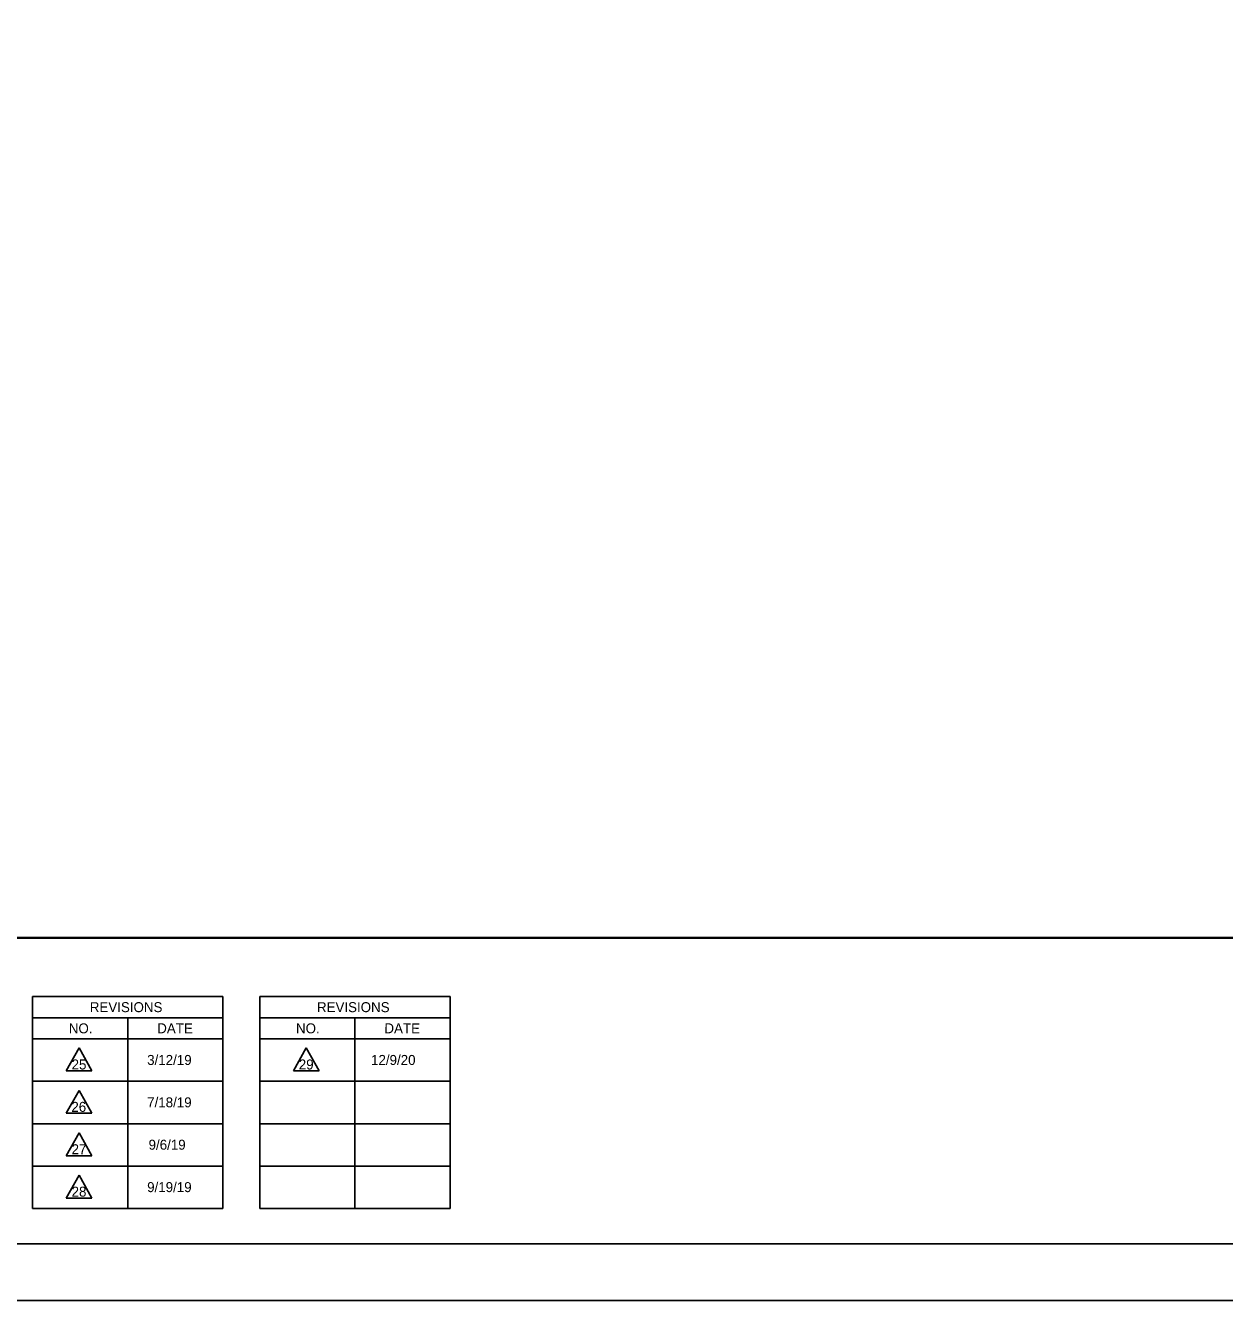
# Model space of a CAD drawing. Extents: x -2251 to 10196, y -13470 to 1199.
# Drawn here: x 750 to 1279, y -2926 to -2363 of the extents above; entities that cross this region are included whole.
import ezdxf

# ---------------------------------------------------------------- set-up
doc = ezdxf.new("R2010")
doc.units = 0
for name, color, linetype in [('RD_SHT_Bndy', 7, 'Continuous'), ('RD_SHT_Iplotshp', 7, 'Continuous'), ('RD_SHT_Misc1', 7, 'Continuous'), ('RD_SHT_Snap', 7, 'Continuous'), ('RD_SHT_TX', 7, 'Continuous'), ('RD_TX_RoadID', 7, 'Continuous')]:
    doc.layers.add(name, color=color, linetype=linetype)

msp = doc.modelspace()

# ---------------------------------------------------------------- linework, layer by layer
at = {"layer": 'RD_SHT_Bndy'}
for p, q in [((103.1, -2900.65), (1778.1, -2900.65)), ((1050.94, -2900.65), (836.06, -2900.65)), ((1791.65, -2925.65), (31.65, -2925.65))]:
    msp.add_line(p, q, dxfattribs=at)
msp.add_lwpolyline([(153.4, -1901.26), (1731.08, -1901.26), (1731.08, -2765.57), (153.4, -2765.57)], close=True, dxfattribs=at)
at = {"layer": 'RD_SHT_Iplotshp'}
msp.add_lwpolyline([(-3.35, -1825.65), (1796.65, -1825.65), (1796.65, -2925.65), (-3.35, -2925.65)], close=True, dxfattribs=at)
at = {"layer": 'RD_SHT_Misc1'}
msp.add_lwpolyline([(1796.65, -2925.65), (1796.68, -1825.65), (96.68, -1825.6), (96.65, -2925.6)], close=True, dxfattribs=at)
at = {"layer": 'RD_SHT_Snap'}
msp.add_lwpolyline([(8.15, -1825.65), (1808.15, -1825.65), (1808.15, -2925.65), (8.15, -2925.65)], close=True, dxfattribs=at)
at = {"layer": 'RD_SHT_TX'}
for p, q in [((837.09, -2791.56), (753.09, -2791.56)), ((753.09, -2791.56), (753.09, -2885.05)), ((837.09, -2885.05), (837.09, -2791.56)), ((937.34, -2791.56), (853.34, -2791.56)), ((853.34, -2791.56), (853.34, -2885.05)), ((937.34, -2885.05), (937.34, -2791.56)), ((837.09, -2800.91), (753.09, -2800.91)), ((795.09, -2885.05), (795.09, -2800.91)), ((937.34, -2800.91), (853.34, -2800.91)), ((895.34, -2885.05), (895.34, -2800.91)), ((837.09, -2810.25), (753.09, -2810.25)), ((937.34, -2810.25), (853.34, -2810.25)), ((773.64, -2814.23), (767.95, -2824.37)), ((773.64, -2814.23), (779.33, -2824.37)), ((873.89, -2814.23), (868.19, -2824.37)), ((873.89, -2814.23), (879.58, -2824.37)), ((837.09, -2828.95), (753.09, -2828.95)), ((767.95, -2824.37), (779.33, -2824.37)), ((937.34, -2828.95), (853.34, -2828.95)), ((868.19, -2824.37), (879.58, -2824.37)), ((773.64, -2832.93), (767.95, -2843.07)), ((773.64, -2832.93), (779.33, -2843.07)), ((767.95, -2843.07), (779.33, -2843.07)), ((837.09, -2847.65), (753.09, -2847.65)), ((773.64, -2851.63), (767.95, -2861.77)), ((773.64, -2851.63), (779.33, -2861.77)), ((937.34, -2847.65), (853.34, -2847.65)), ((767.95, -2861.77), (779.33, -2861.77)), ((837.09, -2866.35), (753.09, -2866.35)), ((937.34, -2866.35), (853.34, -2866.35)), ((773.64, -2870.33), (767.95, -2880.47)), ((773.64, -2870.33), (779.33, -2880.47)), ((837.09, -2885.05), (753.09, -2885.05)), ((767.95, -2880.47), (779.33, -2880.47)), ((937.34, -2885.05), (853.34, -2885.05))]:
    msp.add_line(p, q, dxfattribs=at)
at = {"layer": 'RD_TX_RoadID'}
msp.add_lwpolyline([(150.54, -2765.73), (1733.93, -2765.73), (1733.93, -1962.61), (150.54, -1962.61)], close=True, dxfattribs=at)

# ---------------------------------------------------------------- texts
at = {"layer": 'RD_SHT_TX'}
for s, height, rotation, p in [('REVISIONS', 4.4, 360, (778.38, -2798.43)), ('REVISIONS', 4.4, 360, (878.62, -2798.43)), ('NO.', 4.4, 360, (769.11, -2807.78)), ('DATE', 4.408, 359.7246, (808.11, -2807.75)), ('NO.', 4.4, 360, (869.36, -2807.78)), ('DATE', 4.408, 359.7246, (908.36, -2807.75))]:
    msp.add_text(s, height=height, rotation=rotation, dxfattribs=at).set_placement(p)
for s, p in [('3/12/19', (803.68, -2821.72)), ('12/9/20', (902.48, -2821.72)), ('25', (770.34, -2823.72)), ('29', (870.59, -2823.72)), ('26', (770.24, -2842.42)), ('7/18/19', (803.68, -2840.42)), ('27', (770.34, -2861.12)), ('9/6/19', (804.32, -2859.12)), ('9/19/19', (803.68, -2877.82)), ('28', (770.34, -2879.82))]:
    msp.add_text(s, height=4.4, dxfattribs=at).set_placement(p)

doc.saveas('drawing.dxf')
